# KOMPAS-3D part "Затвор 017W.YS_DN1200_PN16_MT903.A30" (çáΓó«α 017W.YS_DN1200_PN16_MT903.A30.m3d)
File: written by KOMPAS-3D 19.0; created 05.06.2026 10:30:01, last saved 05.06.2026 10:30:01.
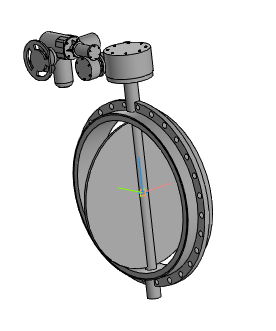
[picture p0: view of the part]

Document properties: Автор: Энергия; Полное имя файла: ..\..\..\3d для проектировщиков\x.x Тип 017W.Y(S) Затвор дисковый поворотный межфланцевый\Затвор 017W.Y(S)_DN32-DN1200_QT.A_MT903.A\Затвор 017W.YS_DN1200_PN16_MT903.A30.a3d

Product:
- Part/product: Затвор 017W.YS_DN1200_PN16_MT903.A30
    Масса: 1176.02

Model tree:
1. Операция без истории:1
